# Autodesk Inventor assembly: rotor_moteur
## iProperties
Created: 2011-01
Part Number: rotor_moteur
Document SubType Name: Assembly
Designer: eric
Mass: 3.37728 g
Surface Area: 27.8948 cm^2
Volume: 3.37728 cm^3
Density: 1 g/cm^3
Norme de conversion: IGES 5.3
Nom du fichier: No Iges File Name specified
Préprocesseur: Autodesk Inventor 2011
Postprocesseur: Build: 342, Release: 2008 SP3 - Date: Tue 05/27/2008
Unités envoyées: MM
Incertitude: 0.01
Author: eric
